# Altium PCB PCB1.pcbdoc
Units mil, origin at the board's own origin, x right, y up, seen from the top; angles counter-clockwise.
Board outline 4730 x 5275 mil, 2 copper layers (Top Layer, Bottom Layer); 23 components, 26 nets, 116 pads, 241 vias.
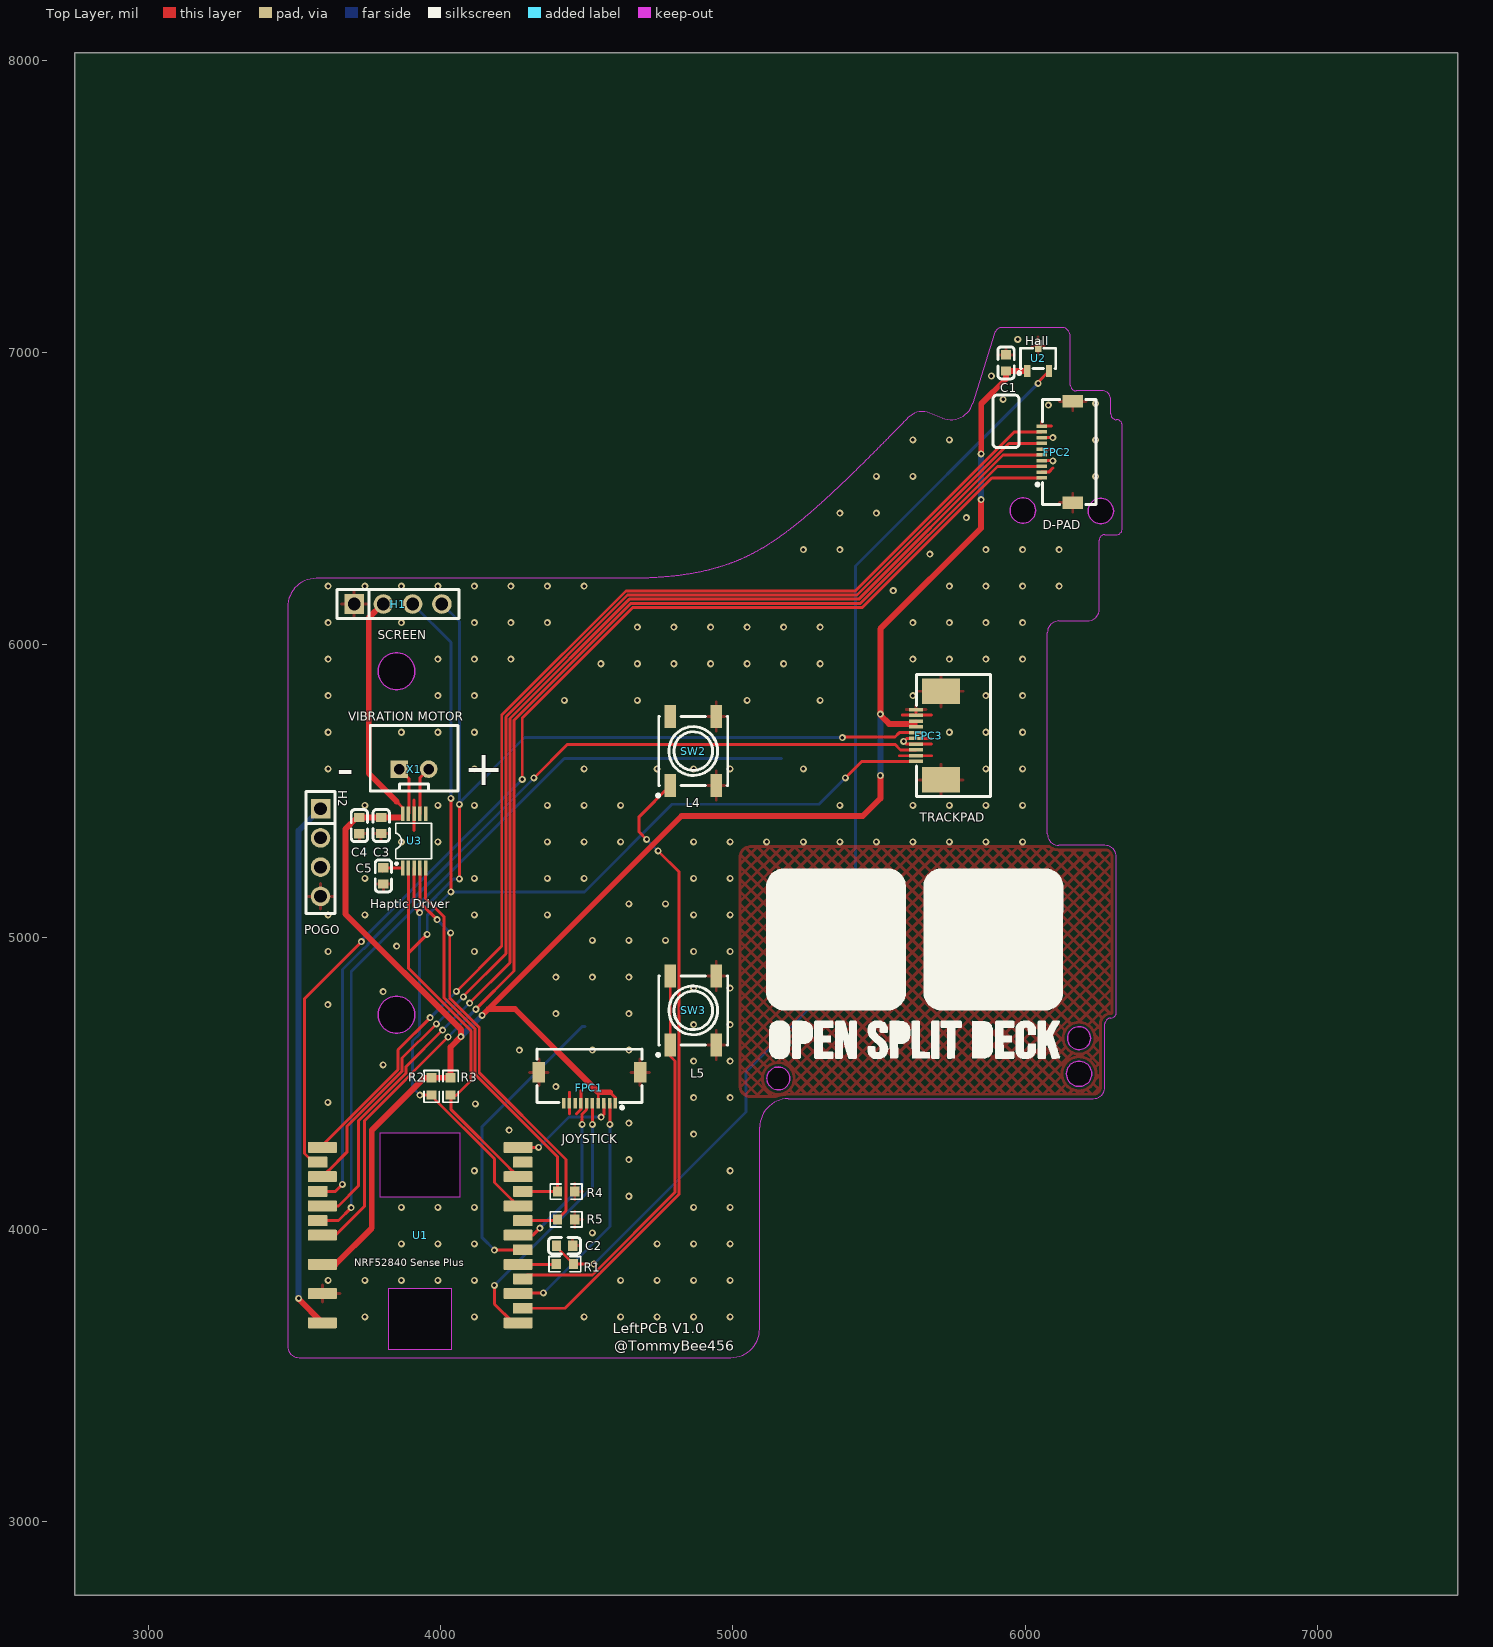
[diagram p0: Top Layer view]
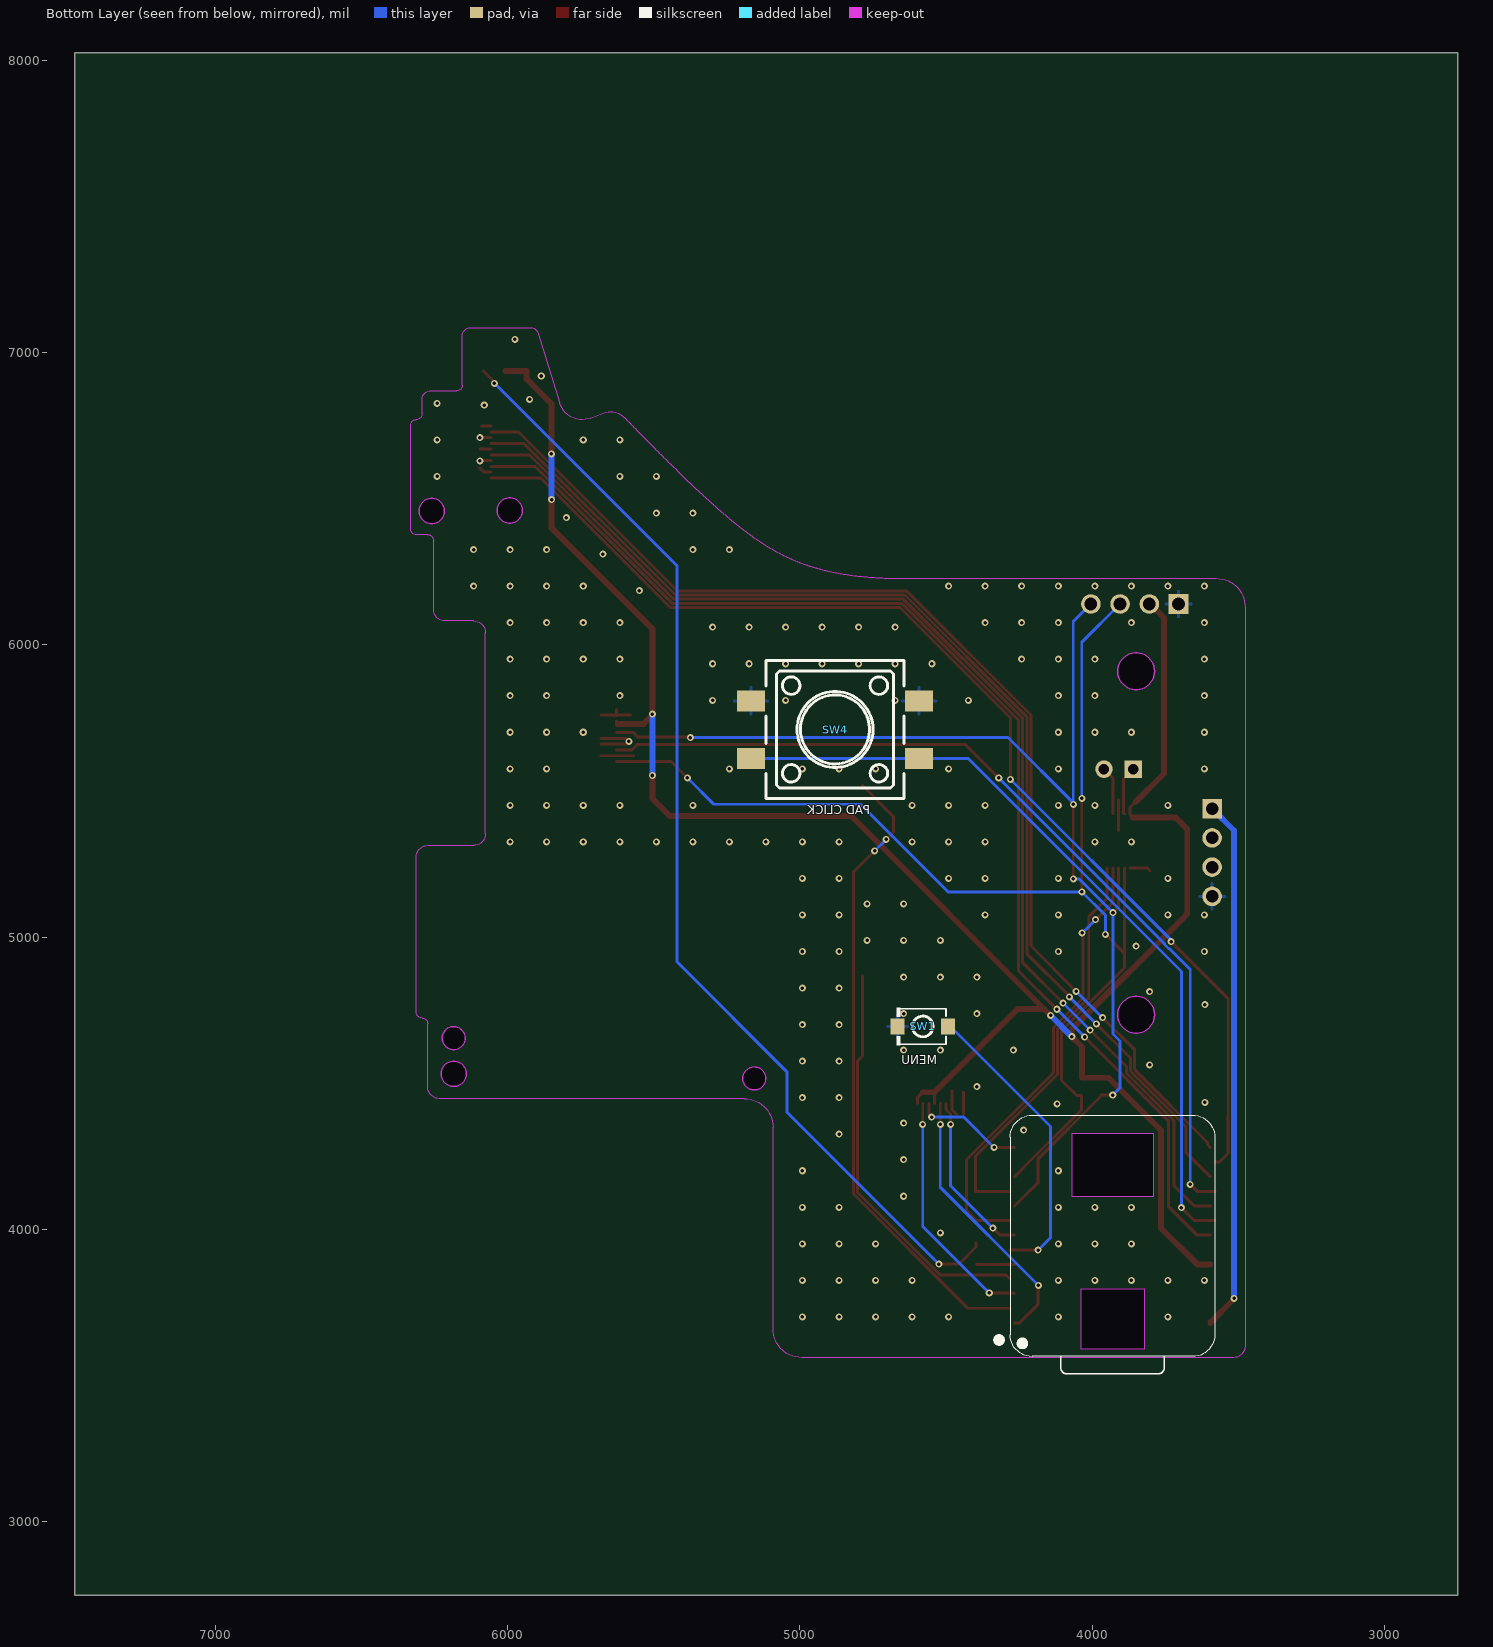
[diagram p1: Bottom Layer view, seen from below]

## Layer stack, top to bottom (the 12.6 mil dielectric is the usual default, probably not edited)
Top Layer: signal copper (thickness not stored)
Dielectric: dielectric 12.6, FR-4, Dk 4.8
Bottom Layer: signal copper (thickness not stored)

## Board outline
7480,2750 2750,2750 2750,8025 7480,8025
cut-out: 5195.47,4517 cw(c5156.1,4517) 5116.73,4517 cw(c5156.1,4517)
cut-out: 6302.57,6458 cw(c6259.26,6458) 6215.95,6458 cw(c6259.26,6458)
cut-out: 6227.91,4533 cw(c6184.61,4533) 6141.3,4533 cw(c6184.61,4533)
cut-out: 6036.03,6460 cw(c5992.72,6460) 5949.41,6460 cw(c5992.72,6460)
cut-out: 6223.98,4655 cw(c6184.61,4655) 6145.24,4655 cw(c6184.61,4655)
cut-out: 3913,5910 cw(c3850,5910) 3787,5910 cw(c3850,5910)
cut-out: 3913,4735 cw(c3850,4735) 3787,4735 cw(c3850,4735)

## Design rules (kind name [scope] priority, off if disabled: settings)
BoardOutlineClearance copperThickness1oz [All] p0: genericclearance=10 ignorepadtopadclearanceinfootprint=FALSE except(0: Arc-SplitContinuation Track-SplitContinuation SMDPad-SplitContinuation THPad-SplitContinuation Via-SplitContinuation Fill-SplitContinuation Poly-SplitContinuation Region-SplitContinuation Text-SplitContinuation; 6: Track-CutoutEdge SMDPad-CutoutEdge THPad-CutoutEdge Via-CutoutEdge Region-CutoutEdge; 11.8: Track-OutlineEdge SMDPad-OutlineEdge THPad-OutlineEdge Via-OutlineEdge Fill-OutlineEdge Region-OutlineEdge Poly-OutlineEdge Text-OutlineEdge Fill-CutoutEdge)
BoardOutlineClearance copperThickness2oz [All] p0: genericclearance=10 ignorepadtopadclearanceinfootprint=FALSE except(0: Arc-SplitContinuation Track-SplitContinuation SMDPad-SplitContinuation THPad-SplitContinuation Via-SplitContinuation Fill-SplitContinuation Poly-SplitContinuation Region-SplitContinuation Text-SplitContinuation; 6: Track-CutoutEdge SMDPad-CutoutEdge THPad-CutoutEdge Via-CutoutEdge Region-CutoutEdge; 11.8: Track-OutlineEdge SMDPad-OutlineEdge THPad-OutlineEdge Via-OutlineEdge Fill-OutlineEdge Region-OutlineEdge Poly-OutlineEdge Text-OutlineEdge Fill-CutoutEdge)
Clearance copperThickness1oz [(InNet('$1N1882') OR InNet('GND') OR InNet('3V3') OR InNet('+5V') OR InNet('STICKCLICK') OR InNet('STICKX') OR InNet('BUMPER') OR InNet('STICKY') OR InNet('START') OR InNet('SCL') OR InNet('SDA') OR InNet('P4') OR InNet('P5') OR InNet('TRIGGER') OR InNet('Y') OR InNet('X') OR InNet('B') OR InNet('A') OR InNet('MODE') OR InNet('HAPTIC_TRIG') OR InNet('DRV_EN') OR InNet('OUT+') OR InNet('OUT-') OR InNet('RDY') OR InNet('PAD_CLICK') OR InNet('$1N6654'))] p1: gap=7 ignorepadtopadclearanceinfootprint=FALSE except(4: Track-Track; 6: Track-SMDPad SMDPad-SMDPad Track-THPad SMDPad-THPad THPad-THPad Track-Via SMDPad-Via THPad-Via Via-Via SMDPad-Fill THPad-Fill Via-Fill Fill-Fill Track-Region SMDPad-Region THPad-Region Via-Region Region-Region Track-Poly SMDPad-Poly THPad-Poly Via-Poly Fill-Poly Region-Poly Poly-Poly Track-Text SMDPad-Text THPad-Text Via-Text Fill-Text Region-Text Poly-Text Text-Text; 6.9: Track-Hole SMDPad-Hole THPad-Hole Via-Hole Fill-Hole Region-Hole Poly-Hole Text-Hole Sheet-Hole; 11.8: Track-Fill Fill-Region Track-Sheet SMDPad-Sheet THPad-Sheet Via-Sheet Fill-Sheet Region-Sheet Poly-Sheet Text-Sheet)
Clearance copperThickness2oz [All] p1: gap=7 ignorepadtopadclearanceinfootprint=FALSE except(6: Track-SMDPad SMDPad-SMDPad Track-THPad SMDPad-THPad THPad-THPad Track-Via SMDPad-Via THPad-Via Via-Via SMDPad-Fill THPad-Fill Via-Fill Fill-Fill Track-Region SMDPad-Region THPad-Region Via-Region Region-Region Track-Poly SMDPad-Poly THPad-Poly Via-Poly Fill-Poly Region-Poly Poly-Poly Track-Text SMDPad-Text THPad-Text Via-Text Fill-Text Region-Text Poly-Text Text-Text; 6.9: Track-Hole SMDPad-Hole THPad-Hole Via-Hole Fill-Hole Region-Hole Poly-Hole Text-Hole Sheet-Hole; 8: Track-Track; 11.8: Track-Fill Fill-Region Track-Sheet SMDPad-Sheet THPad-Sheet Via-Sheet Fill-Sheet Region-Sheet Poly-Sheet Text-Sheet)
DiffPairsRouting differentialPair [All] p1: maxuncoupledlength=10 minlimit=6 maxlimit=6 mostfreqgap=6 toplayer_minwidth=5 toplayer_prefwidth=10 toplayer_maxwidth=100 bottomlayer_minwidth=5 bottomlayer_prefwidth=10 bottomlayer_maxwidth=100
PasteMaskExpansion pasteMaskExpansion [All] p1: expansion=0
PlaneConnect innerPlane [All] p1: planeconnectstyle=Relief reliefexpansion=20 reliefentries=4 reliefconductorwidth=10 reliefairgap=10
PolygonConnect copperRegion [All] p1: connectstyle=Relief reliefentries=4 reliefconductorwidth=10 polygonreliefangle="90 Angle" airgapwidth=10
RoutingVias viaSize [All] p1: viastyle="Through Hole" holewidth=12.0078 minholewidth=11.811 maxholewidth=248.0314 width=24.0158 minwidth=19.685 maxwidth=393.7008
SolderMaskExpansion solderMaskExpansion [All] p1: useseparateexpansions=TRUE expansion=2 expansionbottom=2
Width copperThickness1oz [All] p1: maxlimit=100 minlimit=5 preferedwidth=10
Width copperThickness2oz [All] p1: maxlimit=100 minlimit=8 preferedwidth=10

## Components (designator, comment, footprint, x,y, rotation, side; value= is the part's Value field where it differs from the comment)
C1 "CC0603KRX7R9BB104" C0603 5935,6965 r270 top
C2 "0603B472K500NT" C0603 4425,3945 r180 top
C3 "CC0603KRX7R9BB104" C0603 3797.56,5382.44 r90 top
C4 "CL10A106KP8NNNC" C0603 3723.04,5381.86 r90 top
C5 "CL10A105KB8NNNC" C0603 3805,5210 r90 top
FPC1 "FPC-05F-10PH15" FPC-SMD_10P-P0.50_XUNPU_FPC-05F-10PH15 4510,4485 r180 top
FPC2 "FPC-05F-10PH15" FPC-SMD_10P-P0.50_XUNPU_FPC-05F-10PH15 6110,6660 r90 top
FPC3 "AFC07-S10ECC-00" FPC-SMD_P0.50-10P_LCS-SJ-H2.0 5670,5690 r270 top
H1 "PM254V-11-04-H85" HDR-TH_4P-P2.54-V-F 3855,6140 r0 top
H2 "PM254V-11-04-H85" HDR-TH_4P-P2.54-V-F 3590,5290 r270 top
R1 "0603WAF1000T5E" R0603 4425.66,3882.26 r180 top
R2 "0603WAF2201T5E_C4190" R0603 3970,4490 r90 top
R3 "0603WAF2201T5E_C4190" R0603 4035,4490 r90 top
R4 "0603WAF2003T5E" R0603 4430,4130 r180 top
R5 "0603WAF2003T5E" R0603 4430,4035 r180 top
SW1 "Start" SW-SMD_L3.9-W3.0-P4.45 4580,4695 r0 bottom
SW2 "EVPBFAC1A000" KEY-SMD_4P-L6.0-W6.0-P4.00-LS6.6 4865,5637 r90 top
SW3 "EVPBFAC1A000" KEY-SMD_4P-L6.0-W6.0-P4.00-LS6.6 4865,4750 r90 top
SW4 "TS-1103S-C-I" KEY-SMD_4P-L12.0-W12.0-P5.00-LS15.4 4880,5710 r0 bottom
U1 "XIAO-nRF52840_Plus_SMD" XIAO-nRF52840-Plus-SMD 3930,3955 r180 top
U2 "A1304ELHLX-T" SOT-23-3_L3.0-W1.9-P0.95-LS2.9-BL 6045,6980 r0 top
U3 "DRV2605LDGSR" VSSOP-10_L3.0-W3.0-P0.50-LS4.9-BL 3910,5330 r0 top
X1 "JST" 2JST2.54 3910,5575 r0 top

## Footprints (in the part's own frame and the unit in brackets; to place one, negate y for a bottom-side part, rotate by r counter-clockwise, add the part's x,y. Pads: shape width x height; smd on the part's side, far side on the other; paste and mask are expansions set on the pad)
2JST2.54 [mil]
  rect 60x60 hole 36: 1(-50,0)
  round 60 hole 36: 2(50,0)
  silkscreen extent -150,-75 150,150
C0603 [mm]
  rect 0.8x0.9 smd: 1(-0.7,0) 2(0.7,0)
  silkscreen extent -1.39,-0.71 1.39,0.71
FPC-SMD_10P-P0.50_XUNPU_FPC-05F-10PH15 [mm]
  rect 0.3x0.9 smd: 1(-2.25,1.35) 2(-1.75,1.35) 3(-1.25,1.35) 4(-0.75,1.35) 5(-0.25,1.35) 6(0.25,1.35) 7(0.75,1.35) 8(1.25,1.35) 9(1.75,1.35) 10(2.25,1.35)
  rect 1.1x1.8 smd: 11(4.4,-1.35) 12(-4.4,-1.35)
  silkscreen extent -4.56,-3.36 4.55,1.84
FPC-SMD_P0.50-10P_LCS-SJ-H2.0 [mm]
  rect 0.3x1.2 smd: 1(2.25,-1.085) 2(1.75,-1.085) 3(1.25,-1.085) 4(0.75,-1.085) 5(0.25,-1.085) 6(-0.25,-1.085) 7(-0.75,-1.085) 8(-1.25,-1.085) 9(-1.75,-1.085) 10(-2.25,-1.085)
  rect 2.2x3.3 smd: 11(-3.85,1.085) 12(3.85,1.085)
  silkscreen extent -5.3,-1.04 5.3,5.37
HDR-TH_4P-P2.54-V-F [mm]
  rect 1.7x1.7 hole 1.1: 1(-3.81,0)
  round 1.7 hole 1.1: 2(-1.27,0) 3(1.27,0) 4(3.81,0)
  silkscreen extent -5.29,-1.27 5.29,1.27
KEY-SMD_4P-L6.0-W6.0-P4.00-LS6.6 [mm]
  rect 2x1 smd: 1(-3,2) 2(3,2) 3(-3,-2) 4(3,-2)
  silkscreen extent -3.99,-3 3,3.18
KEY-SMD_4P-L12.0-W12.0-P5.00-LS15.4 [mm]
  rect 2.4x1.8 smd: 1(-7.3,2.5) 2(7.3,2.5) 3(-7.3,-2.5) 4(7.3,-2.5)
  silkscreen extent -6,-6.02 6,5.98
R0603 [mil]
  rect 31.75x34.02 smd: 1(-29.66,0) 2(29.66,0)
  silkscreen extent -55,-26 55,26
SOT-23-3_L3.0-W1.9-P0.95-LS2.9-BL [mil]
  rect 20.95x40.85 smd: 1(-37.4,-43.36) 2(37.4,-43.36) 3(0.01,43.36)
  silkscreen extent -70,-55 60,35
SW-SMD_L3.9-W3.0-P4.45 [mm]
  rect 1.23x1.36 smd: 1(-2.185,0) 2(2.185,0)
  silkscreen extent -2.03,-1.62 2.25,1.62
VSSOP-10_L3.0-W3.0-P0.50-LS4.9-BL [mm]
  rect 0.3x1.3 smd: 1(-1,-2.35) 2(-0.5,-2.35) 3(0,-2.35) 4(0.5,-2.35) 5(1,-2.35) 6(1,2.35) 7(0.5,2.35) 8(0,2.35) 9(-0.5,2.35) 10(-1,2.35)
  silkscreen extent -1.62,-2.08 1.52,1.54
XIAO-nRF52840-Plus-SMD [mm]
  rrect20% 2.532x0.95 smd: 1(-8.533,6.958) 2(-8.533,4.418) 3(-8.533,1.878) 4(-8.533,-0.662) 5(-8.533,-3.202) 6(-8.533,-5.742) 7(-8.533,-8.282) 8(8.477,-8.282) 9(8.477,-5.742) 10(8.477,-3.202) 11(8.477,-0.662) 12(8.477,1.878) 13(8.477,4.418) 14(8.477,6.958)
  rrect20% 1.732x0.95 smd: 15(-8.933,5.688) 16(-8.933,3.148) 17(-8.933,0.608) 18(-8.933,-1.932) 19(-8.933,-4.472) 20(-8.933,-7.012) 21(8.877,-7.012) 22(8.877,-4.472) 23(8.877,-1.932)
  Board Outline Layer lines w0.025: 3.5,-4 3.5,-9.5 -3.5,-9.5 -3.5,-4 3.5,-4 ; 2.75,9.25 2.75,4 -2.75,4 -2.75,9.25 2.75,9.25
  Board Outline Layer region: -3.5,-9.5 3.5,-9.5 3.5,-4 -3.5,-4
  Board Outline Layer region: -2.75,4 2.75,4 2.75,9.25 -2.75,9.25
  Multi-Layer board cut-out: -3.5,-9.5 3.5,-9.5 3.5,-4 -3.5,-4
  Multi-Layer board cut-out: -2.75,4 2.75,4 2.75,9.25 -2.75,9.25

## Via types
v1: diameter 24.02, hole 12.01, Top Layer to Bottom Layer, 241 vias

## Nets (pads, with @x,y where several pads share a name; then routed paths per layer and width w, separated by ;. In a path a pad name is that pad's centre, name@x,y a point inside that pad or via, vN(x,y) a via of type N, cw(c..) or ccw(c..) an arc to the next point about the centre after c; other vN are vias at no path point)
3V3: C1.2 C3.2 C4.2 FPC1.1 FPC1.4 FPC3.7 FPC3.8 H1.2 R2.2 R3.2 U1.12 U2.1 U3.10 | length 7185.1
  Top Layer w10: 3850,5465 3870.62,5444.38 U3.10 3870.62,5420 3860.62,5410 ; FPC1.4 4540,4432.32 4540,4470 ; 4580,4470 4598.58,4451.42 FPC1.1 ; FPC3.7@5627.28,5724.52 FPC3.8
  Top Layer w20: U1.12 3641.07,3881.07 3765,4005 3765,4340 3944.66,4519.66 R2.2 R3.2 4035,4625 v1(4070,4660) 4070,4685 3675,5080 3675,5370 3714.42,5409.42 C4.2 3723.62,5410 C3.2 3860.62,5410 ; H1.2 3801.96,6140 3755,6093.04 3755,5560 3850,5465 ; v1(4142.43,4732.57) 4164.85,4755 ; 4580,4470 4540,4470 4255,4755 4164.85,4755 ; v1(5505,5553.42) 5505,5475 5445,5415 4824.85,5415 4164.85,4755 ; 5621.81,5730 5535.1,5730 5505,5760.1 v1(5505,5762.99) 5505,6055 5849.36,6399.36 v1(5849.36,6497.38) ; v1(5850,6653.4) 5850,6825 5935,6910 C1.2 6006.8,6937.44 U2.1
  Bottom Layer w20: v1(4070,4660) 4070,4660.15 v1(4142.43,4732.57) ; v1(5505,5553.42) v1(5505,5762.99) ; v1(5849.36,6497.38) 5849.36,6652.76 v1(5850,6653.4)
$1N1882: C5.2 U3.1 | length 72.6
  Top Layer w10: C5.2@3802.42,5226.9 3813,5237.48 U3.1
$1N6654: R1.2 U1.3 | length 130.6
  Top Layer w10: U1.3 4394.81,3881.07 R1.2
+5V: H2.1 U1.14 | length 1823.7
  Top Layer w20: v1(3515,3765) 3515,3762.32 U1.14
  Bottom Layer w20: v1(3515,3765) 3515,5365 H2.1
A: FPC2.7 U1.9 | length 4053.5
  Top Layer w10: U1.9 3616.56,4201.38 3616.95,4201.38 3680,4264.43 3680,4352.36 3869.02,4541.38 3869.02,4586.59 v1(3986.21,4703.79) ; v1(4078.71,4796.29) 4078.71,4798.71 4224.02,4944.02 4224.02,5754.02 4640.49,6170.49 5425.49,6170.49 5944.53,6689.53 FPC2.7
  Bottom Layer w10: v1(3986.21,4703.79) v1(4078.71,4796.29)
B: FPC2.3 U1.11 | length 4223.8
  Top Layer w10: U1.11 3641.07,3981.07 3740,4080 3740,4372.72 v1(4026.14,4658.86) ; v1(4121.21,4753.79) 4252.05,4884.62 4252.05,5742.4 4652.1,6142.46 5437.1,6142.46 5905.43,6610.79 FPC2.3
  Bottom Layer w10: v1(4026.14,4658.86) 4121.07,4753.79 v1(4121.21,4753.79)
BUMPER: FPC1.3 U1.7 | length 377.8
  Top Layer w10: U1.7 v1(4336.07,4281.07) ; v1(4550,4385) 4559.21,4394.21 FPC1.3
  Bottom Layer w10: v1(4336.07,4281.07) 4440,4385 v1(4550,4385)
DRV_EN: R4.2 U1.19 U3.5 | length 1412.9
  Top Layer w10: U3.5 3949.38,5133.14 4012.01,5070.51 4012.01,4792.81 4119.02,4685.81 4119.02,4530.98 4400,4250 R4.2@4400,4130.34 ; U1.19 4399.27,4131.07 R4.2@4400,4130.34 ; R4.2 R4.2@4400,4130.34
GND: C1.1 C2.1 C3.1 C4.1 C5.1 FPC1.7 FPC1.9 FPC1.11 FPC1.12 FPC2.2 FPC2.4 FPC2.6 FPC2.8 FPC2.10 FPC2.11 FPC2.12 FPC3.2 FPC3.4 FPC3.5 FPC3.9 FPC3.10 FPC3.11 FPC3.12 H1.1 H2.4 R4.1 R5.1 SW1.2 SW2.3 SW2.4 SW3.3 SW3.4 SW4.3 SW4.4 U1.13 U2.3 U3.8 | length 886.1
  Top Layer w10: 3910.01,5365 U3.8 3910.01,5470 ; 4441.1,4395 FPC1.9 4441.1,4470 ; 4465,4395 4480.47,4410.47 FPC1.7 4480.47,4475 ; 5570,5621.1 FPC3.2 5680,5621.1 ; 5580,5760 FPC3.9@5627.28,5760 ; FPC3.9 FPC3.9@5627.28,5760 ; FPC3.10 FPC3.9@5627.28,5760 ; 5680,5660.47 FPC3.4 5594.53,5660.47 v1(5585,5670) 5595.15,5680.15 FPC3.5 5680,5680.15 ; 5680,5760 FPC3.9@5627.28,5760 ; FPC2.2 6081.1,6591.1 6095,6605 ; FPC2.4 6094.53,6630.47 v1(6095,6630) ; FPC2.6 6095,6669.84 ; FPC2.8 6094.73,6709.21 v1(6095,6708.94) ; FPC2.10 6090,6748.58
  other v1: 3741.34,3701.34 4116.34,3701.34 4491.34,3701.34 4616.34,3701.34 4741.34,3701.34 4866.34,3701.34 4991.34,3701.34 3616.34,3826.34 3741.34,3826.34 3866.34,3826.34 3991.34,3826.34 4116.34,3826.34 4616.34,3826.34 4741.34,3826.34 4866.34,3826.34 4991.34,3826.34 3866.34,3951.34 3991.34,3951.34 4116.34,3951.34 4741.34,3951.34 4866.34,3951.34 4991.34,3951.34 4520.06,3989.1 3866.34,4076.34 3991.34,4076.34 4116.34,4076.34 4866.34,4076.34 4991.34,4076.34 4645.06,4114.1 4116.34,4201.34 4991.34,4201.34 4645.06,4239.1 4866.34,4326.34 4235,4340 4645.06,4364.1 4120,4430 3615,4434.94 4866.34,4451.34 4991.34,4451.34 4395.06,4489.1 3804.1,4563.87 4866.34,4576.34 4991.34,4576.34 4270.06,4614.1 4520.06,4614.1 4645.06,4614.1 4866.34,4701.34 4991.34,4701.34 4395.06,4739.1 4645.06,4739.1 3615,4770 3804.1,4813.87 4866.34,4826.34 4991.34,4826.34 4395.06,4864.1 4520.06,4864.1 4645.06,4864.1 3616.34,4951.34 4116.34,4951.34 4866.34,4951.34 4991.34,4951.34 3850,4970 4520.06,4989.1 4645.06,4989.1 4770.06,4989.1 3616.34,5076.34 3741.34,5076.34 4116.34,5076.34 4366.34,5076.34 4866.34,5076.34 4991.34,5076.34 4645.06,5114.1 4770.06,5114.1 3741.34,5201.34 4116.34,5201.34 4366.34,5201.34 4491.34,5201.34 4866.34,5201.34 4991.34,5201.34 3866.34,5326.34 3991.34,5326.34 4366.34,5326.34 4491.34,5326.34 4616.34,5326.34 4866.34,5326.34 4991.34,5326.34 5116.34,5326.34 5241.34,5326.34 5366.34,5326.34 5491.34,5326.34 5616.34,5326.34 5741.34,5326.34 5866.34,5326.34 5991.34,5326.34 3741.34,5451.34 3991.34,5451.34 4116.34,5451.34 4366.34,5451.34 4491.34,5451.34 4616.34,5451.34 5366.34,5451.34 5616.34,5451.34 5741.34,5451.34 5866.34,5451.34 5991.34,5451.34 3616.34,5576.34 4116.34,5576.34 4491.34,5576.34 4741.34,5576.34 4866.34,5576.34 4991.34,5576.34 5241.34,5576.34 5866.34,5576.34 5991.34,5576.34 3616.34,5701.34 3866.34,5701.34 3991.34,5701.34 4116.34,5701.34 5741.34,5701.34 5866.34,5701.34 5991.34,5701.34 4424.1,5810.65 4674.1,5810.65 5049.1,5810.65 5299.1,5810.65 3616.34,5826.34 3991.34,5826.34 4116.34,5826.34 5616.34,5826.34 5866.34,5826.34 5991.34,5826.34 4549.1,5935.65 4674.1,5935.65 4799.1,5935.65 4924.1,5935.65 5049.1,5935.65 5174.1,5935.65 5299.1,5935.65 3616.34,5951.34 3991.34,5951.34 4116.34,5951.34 4241.34,5951.34 5616.34,5951.34 5741.34,5951.34 5866.34,5951.34 5991.34,5951.34 4674.1,6060.65 4799.1,6060.65 4924.1,6060.65 5049.1,6060.65 5174.1,6060.65 5299.1,6060.65 3616.34,6076.34 3866.34,6076.34 4116.34,6076.34 4241.34,6076.34 4366.34,6076.34 5616.34,6076.34 5741.34,6076.34 5866.34,6076.34 5991.34,6076.34 5549.1,6185.65 3616.34,6201.34 3741.34,6201.34 3866.34,6201.34 3991.34,6201.34 4116.34,6201.34 4241.34,6201.34 4366.34,6201.34 4491.34,6201.34 5741.34,6201.34 5866.34,6201.34 5991.34,6201.34 6116.34,6201.34 5674.1,6310.65 5241.34,6326.34 5366.34,6326.34 5866.34,6326.34 5991.34,6326.34 6116.34,6326.34 5799.1,6435.65 5366.34,6451.34 5491.34,6451.34 5491.34,6576.34 5616.34,6576.34 6241.34,6576.34 5616.34,6701.34 5741.34,6701.34 6241.34,6701.34 6080,6820 6241.34,6826.34 5925,6840 5885,6920 5975,7045
HAPTIC_TRIG: R5.2 U1.18 U3.4 | length 1545.3
  Top Layer w10: U3.4 3929.68,5119.33 v1(3989.02,5060) ; v1(4035,5015) 4032.01,5012.01 4032.01,4792.63 4133.03,4691.61 4133.03,4536.79 4430,4239.82 4430,4064.66 R5.2 4396.41,4031.07 U1.18
  Bottom Layer w10: v1(3989.02,5060) 4034.02,5015 v1(4035,5015)
MODE: SW1.1 U1.17 | length 1030.1
  Top Layer w10: v1(4185,3930) 4280.61,3930 U1.17
  Bottom Layer w10: v1(4185,3930) 4143.03,3971.97 4143.03,4353.03 4485,4695 SW1.1
OUT+: U3.7 X1.2 | length 165
  Top Layer w10: U3.7 3929.68,5544.69 X1.2
OUT-: U3.9 X1.1 | length 167.4
  Top Layer w10: X1.1 3893.12,5541.88 3893.12,5425.32 U3.9
P4: SW2.1 U1.15 | length 2194.9
  Top Layer w10: U1.15 4426.14,3731.07 4816.93,4121.85 4816.93,5223.07 v1(4744.72,5295.28) ; v1(4705.13,5334.87) 4680,5360 4680,5412.63 SW2.1
  Bottom Layer w10: v1(4705.13,5334.87) v1(4744.72,5295.28)
P5: SW3.1 SW3.2 U1.16 | length 1391.4
  Top Layer w10: U1.16 4295.61,3845 4520.25,3845 4802.91,4127.66 4802.91,4577.09 4786.26,4593.74 SW3.2
PAD_CLICK: SW4.1 SW4.2 U1.23 | length 2714.6
  Top Layer w10: U1.23 3651.07,4031.07 v1(3695,4075)
  Bottom Layer w10: v1(3695,4075) 3695,4882.52 4424.06,5611.57 SW4.1 SW4.2
RDY: FPC3.3 U1.22 | length 3120.1
  Top Layer w10: U1.22 3641.07,4131.07 v1(3665,4155) ; v1(4320,5545) 4435,5660 5555,5660 5574.22,5640.78 FPC3.3
  Bottom Layer w10: v1(3665,4155) 3665,4890 3737.01,4962.01 3739.52,4962.01 3752.99,4975.48 3752.99,4977.99 v1(4320,5545)
SCL: FPC3.1 H1.3 R3.1 U1.6 U3.2 | length 4364.5
  Top Layer w10: U3.2 3890.32,4945.31 ; v1(3955,5010) 3890.32,4945.31 ; v1(4035.98,5155) v1(4035.98,5475) ; U1.6 4245.62,4201.38 4245.23,4201.38 4236.6,4210.01 4236.6,4210.4 4036.82,4410.18 4036.82,4458.45 4053.45,4458.45 4105,4510 4105,4680 3890.32,4894.69 3890.32,4945.31 ; v1(5385,5545) 5441.41,5601.41 FPC3.1
  Bottom Layer w10: H1.3 4035.98,6009.02 v1(4035.98,5475) ; v1(3955,5010) 3955,5075 4035,5155 v1(4035.98,5155) 4492.75,5155 4792.75,5455 5295,5455 v1(5385,5545)
SDA: FPC3.6 H1.4 R2.1 U1.5 U3.3 | length 4157.8
  Top Layer w10: U3.3 3910,5103.31 v1(3929.15,5084.15) ; v1(3930,4460.34) R2.1 3970,4457.18 4185,4242.18 4185,4161.61 4245.23,4101.38 4245.62,4101.38 U1.5 ; v1(4065,5200) v1(4065,5455) ; v1(5375,5682.99) 5377.01,5685 5555,5685 5569.84,5699.84 FPC3.6
  Bottom Layer w10: v1(3930,4460.34) 3905,4485.34 3905,4645 3929.15,4669.15 v1(3929.15,5084.15) 4045,5200 v1(4065,5200) ; H1.4 4065,6080 v1@4065,5460 ; v1(4065,5455) v1@4065,5460 ; v1(5375,5682.99) 4287.99,5682.99 v1@4065,5460
START: FPC2.9 U1.8 | length 3981.3
  Top Layer w10: U1.8 3606.25,4291.07 3606.25,4298.43 3855,4547.18 3855,4615 v1(3965,4725) ; v1(4055,4815) 4210,4970 4210,5760 4635,6185 5419.12,6185 5963.02,6728.9 FPC2.9
  Bottom Layer w10: v1(3965,4725) v1(4055,4815)
STICKCLICK: FPC1.6 U1.4 | length 577.2
  Top Layer w10: U1.4 4316.07,3981.07 v1(4340,4005) ; v1(4485,4360) 4485,4395 4500.16,4410.16 FPC1.6
  Bottom Layer w10: v1(4340,4005) 4485,4150 v1(4485,4360)
STICKX: FPC1.5 U1.1 | length 933.7
  Top Layer w10: v1(4184.29,3809.29) 4185,3808.58 4185,3745 4248.93,3681.07 U1.1 ; FPC1.5 4520,4431.69 v1(4520,4360)
  Bottom Layer w10: v1(4184.29,3809.29) 4520,4145 v1(4520,4360)
STICKY: FPC1.2 U1.2 | length 830.6
  Top Layer w10: U1.2 4268.43,3783.57 v1(4352.5,3783.57) ; FPC1.2 4580,4430.75 v1(4580,4360)
  Bottom Layer w10: v1(4352.5,3783.57) 4580,4011.07 v1(4580,4360)
TRIGGER: C2.2 R1.1 U2.2 | length 3865.9
  Top Layer w10: C2.2@4397.44,3955 4397.44,3940.15 R1.1 v1(4525,3882.26) ; v1(6045,6895) 6045,6899.24 U2.2
  Bottom Layer w10: v1(4525,3882.26) 5045,4402.26 5045,4540 5420,4915 5420,6270 v1(6045,6895)
X: FPC2.5 U1.10 | length 4157.6
  Top Layer w10: U1.10 3651.07,4081.07 3720,4150 3720,4372.54 3883.03,4535.57 3883.03,4558.18 v1(4007.43,4682.57) ; v1(4100,4775) 4238.03,4913.03 4238.03,5748.21 4646.3,6156.48 5431.3,6156.48 5924.98,6650.16 FPC2.5
  Bottom Layer w10: v1(4007.43,4682.57) 4007.57,4682.57 v1(4100,4775)
Y: FPC2.1 U1.21 | length 3973.2
  Top Layer w10: U1.21 3564.36,4231.07 3535.42,4260.01 3535.42,4389.58 3535,4390 3535,4790 v1(3730,4985) ; v1(4280,5540) 4280,5750.54 4657.91,6128.45 5443.45,6128.45 5886.42,6571.42 FPC2.1
  Bottom Layer w10: v1(3730,4985) 3730,4990 v1(4280,5540)
pads on no net: FPC1.8 FPC1.10 H2.2 H2.3 SW2.2 U1.20 U3.6

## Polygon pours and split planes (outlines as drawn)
GND on Top Layer (hatched 45Degree grid 30 track 10, pour order 0): 5060,5315 6275,5315 cw(c6275,5275) 6315,5275 6315,4490 cw(c6275,4490) 6275,4450 5060,4450 cw(c5060,4490) 5020,4490 5020,5275 cw(c5060,5275)
GND on Bottom Layer (solid, remove dead copper, pour order 4): 3000,7470 3000,3340 3340,3000 6975,3000 7230,3255 7230,7495 6955,7770 3300,7770
GND on Top Layer (solid, remove dead copper, pour order 2): 3345,6370 3345,3470 3420,3395 5285,3395 5275.58,4455 5051.78,4455 5026.72,4468.8 5025,4480.48 5025,5280 5036.44,5303.28 5055.67,5310.21 6205.29,5310.21 6555,5666.23 6555,7775 4750,7775

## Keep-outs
Board Outline Layer:
  circle w1: c5156.1,4517 r39.37
  region: 5195.47,4517 cw(c5156.1,4517) 5116.73,4517 cw(c5156.1,4517)
  circle w1: c6259.26,6458 r43.31
  region: 6302.57,6458 cw(c6259.26,6458) 6215.95,6458 cw(c6259.26,6458)
  circle w1: c6184.61,4533 r43.31
  region: 6227.91,4533 cw(c6184.61,4533) 6141.3,4533 cw(c6184.61,4533)
  circle w1: c5992.72,6460 r43.31
  region: 6036.03,6460 cw(c5992.72,6460) 5949.41,6460 cw(c5992.72,6460)
  circle w1: c6184.61,4655 r39.37
  region: 6223.98,4655 cw(c6184.61,4655) 6145.24,4655 cw(c6184.61,4655)
  circle w1: c3850,5910 r63
  region: 3913,5910 cw(c3850,5910) 3787,5910 cw(c3850,5910)
  circle w1: c3850,4735 r63
  region: 3913,4735 cw(c3850,4735) 3787,4735 cw(c3850,4735)
  lines w3.9: 3752.84,3562.24 4107.17,3562.24
  lines w3.94: 3752.84,3562.24 3516.61,3562.24 cw(c3516.61,3601.61) 3477.24,3601.61 3477.24,6129.05 cw(c3575.67,6129.05) 3575.67,6227.48 4638.66,6227.48 4643.16,6227.48 4647.63,6227.5 4652.08,6227.52 4656.51,6227.56 4660.92,6227.61 4665.3,6227.66 4669.67,6227.73 4674.01,6227.81 4678.34,6227.9 4682.64,6228 4686.92,6228.11 4691.18,6228.23 4695.41,6228.36 4699.63,6228.5 4703.83,6228.65 4708,6228.81 4712.16,6228.98 4716.29,6229.17 4720.4,6229.36 4724.49,6229.56 4728.57,6229.78 4732.62,6230 4736.65,6230.23 4740.66,6230.48 4744.64,6230.73 4748.61,6231 4752.56,6231.28 4756.49,6231.56 4760.4,6231.86 4764.29,6232.17 4768.16,6232.48 4772,6232.81 4775.83,6233.15 4779.64,6233.5 4783.43,6233.86 4787.2,6234.23 4790.95,6234.6 4794.69,6234.99 4798.4,6235.4 4802.09,6235.81 4805.77,6236.23 4809.43,6236.66 4813.06,6237.1 4816.68,6237.55 4820.28,6238.02 4823.87,6238.49 4827.43,6238.97 4830.98,6239.47 4834.51,6239.97 4838.02,6240.48 4841.51,6241.01 4844.99,6241.54 4848.45,6242.09 4851.89,6242.65 4855.32,6243.21 4858.73,6243.79 4862.12,6244.38 4865.49,6244.98 4868.85,6245.58 4872.19,6246.2 4875.52,6246.83 4878.83,6247.47 4882.13,6248.12 4885.4,6248.78 4888.67,6249.46 4891.92,6250.14 4895.15,6250.83 4898.37,6251.53 4901.57,6252.25 4904.76,6252.97 4907.93,6253.7 4911.09,6254.45 4914.24,6255.21 4917.37,6255.97 4920.49,6256.75 4923.59,6257.54 4926.68,6258.34 4929.76,6259.15 4932.82,6259.97 4935.87,6260.8 4938.91,6261.64 4941.94,6262.49 4944.95,6263.36 4947.95,6264.23 4950.94,6265.12 4953.91,6266.01 4956.88,6266.92 4959.83,6267.84 4962.77,6268.77 4965.7,6269.71 4968.62,6270.66 4971.53,6271.62 4974.43,6272.59 4977.32,6273.58 4980.2,6274.57 4983.06,6275.58 4985.92,6276.6 4988.77,6277.63 4991.61,6278.67 4994.43,6279.72 4997.25,6280.78 5000.06,6281.86 5002.87,6282.94 5005.66,6284.04 5008.44,6285.15 5011.22,6286.27 5013.99,6287.41 5016.75,6288.55 5019.51,6289.71 5022.25,6290.87 5024.99,6292.05 5027.72,6293.24 5030.45,6294.45 5033.17,6295.66 5035.88,6296.89 5038.58,6298.13 5041.28,6299.38 5043.98,6300.64 5046.67,6301.92 5049.35,6303.21 5052.03,6304.51 5054.7,6305.82 5057.37,6307.15 5060.03,6308.48 5062.69,6309.83 5065.35,6311.19 5068,6312.57 5070.65,6313.96 5073.29,6315.36 5075.93,6316.77 5078.57,6318.2 5081.2,6319.64 5083.83,6321.09 5086.46,6322.56 5089.09,6324.03 5091.71,6325.53 5094.34,6327.03 5096.96,6328.55 5099.57,6330.08 5102.19,6331.62 5104.81,6333.18 5107.43,6334.76 5110.04,6336.34 5112.65,6337.94 5115.27,6339.56 5117.88,6341.18 5120.5,6342.82 5123.11,6344.48 5125.73,6346.15 5128.34,6347.83 5130.96,6349.53 5133.58,6351.24 5136.2,6352.97 5138.82,6354.71 5141.44,6356.47 5144.06,6358.24 5146.69,6360.02 5149.32,6361.82 5151.95,6363.64 5154.58,6365.47 5157.22,6367.31 5159.86,6369.18 5162.5,6371.05 5165.15,6372.94 5167.8,6374.85 5170.46,6376.77 5173.12,6378.71 5175.78,6380.66 5178.45,6382.63 5181.12,6384.62 5183.8,6386.62 5186.48,6388.64 5189.17,6390.67 5191.86,6392.72 5194.56,6394.78 5197.27,6396.87 5199.98,6398.97 5202.7,6401.08 5205.42,6403.21 5208.16,6405.36 5210.9,6407.53 5213.64,6409.71 5216.39,6411.91 5219.16,6414.13 5221.92,6416.37 5224.7,6418.62 5227.49,6420.89 5230.28,6423.18 5233.08,6425.48 5235.89,6427.8 5238.71,6430.15 5241.54,6432.5 5244.38,6434.88 5247.23,6437.28 5250.08,6439.69 5252.95,6442.12 5255.83,6444.57 5258.71,6447.04 5261.61,6449.53 5264.52,6452.04 5267.44,6454.57 5270.37,6457.11 5273.31,6459.68 5276.27,6462.26 5279.23,6464.86 5282.21,6467.49 5285.2,6470.13 5288.2,6472.79 5291.21,6475.47 5294.24,6478.18 5297.28,6480.9 5300.33,6483.64 5303.39,6486.4 5306.47,6489.18 5309.56,6491.99 5312.66,6494.81 5315.78,6497.66 5318.91,6500.52 5322.06,6503.41 5325.22,6506.31 5328.39,6509.24 5331.58,6512.19 5334.79,6515.16 5338.01,6518.16 5341.24,6521.17 5344.49,6524.2 5347.76,6527.26 5351.04,6530.34 5354.33,6533.44 5357.64,6536.56 5360.97,6539.71 5364.32,6542.88 5367.68,6546.07 5371.05,6549.28 5374.45,6552.51 5377.86,6555.77 5381.28,6559.05 5384.73,6562.35 5388.19,6565.68 5391.67,6569.03 5395.16,6572.4 5398.68,6575.8 5402.21,6579.21 5405.76,6582.66 5409.33,6586.12 5412.91,6589.61 5416.52,6593.12 5420.14,6596.66 5423.78,6600.22 5427.44,6603.81 5431.12,6607.41 5434.82,6611.05 5438.54,6614.7 5442.27,6618.39 5446.03,6622.09 5449.8,6625.82 5453.6,6629.58 5457.41,6633.36 5461.24,6637.16 5465.1,6640.99 5468.97,6644.84 5472.86,6648.72 5476.78,6652.63 5480.71,6656.55 5484.66,6660.51 5488.64,6664.49 5492.63,6668.49 5496.65,6672.52 5500.69,6676.58 5504.74,6680.66 5508.82,6684.76 5512.92,6688.9 5517.04,6693.05 5521.18,6697.24 5525.34,6701.45 5529.52,6705.68 5533.73,6709.94 5537.95,6714.23 5542.2,6718.54 5546.46,6722.88 5550.75,6727.24 5555.06,6731.63 5559.39,6736.05 5563.75,6740.49 5568.12,6744.96 5572.52,6749.45 5576.94,6753.97 5581.38,6758.52 5585.84,6763.09 5590.32,6767.69 5594.82,6772.32 5599.35,6776.97 cw(c5648.74,6728.93) 5673.87,6793.08 5717.07,6776.16 ccw(c5745.79,6849.47) 5821.02,6826.22 5894.84,7065.05 cw(c5923.05,7056.33) 5923.05,7085.86 6125.55,7085.86 cw(c6125.55,7056.33) 6155.08,7056.33 6155.08,6889.01 ccw(c6174.76,6889.01) 6174.76,6869.32 6263.35,6869.32 cw(c6263.35,6839.8) 6292.87,6839.8 6292.87,6790.58 ccw(c6312.56,6790.58) 6312.56,6770.9 cw(c6312.56,6751.21) 6332.24,6751.21 6332.24,6396.88 cw(c6312.56,6396.88) 6312.56,6377.2 6273.19,6377.2 ccw(c6273.19,6357.51) 6253.5,6357.51 6253.5,6121.29 cw(c6214.13,6121.29) 6214.13,6081.92 6115.71,6081.92 ccw(c6115.71,6042.55) 6076.34,6042.55 6076.34,5353.58 ccw(c6115.71,5353.58) 6115.71,5314.21 6273.19,5314.21 cw(c6273.19,5274.84) 6312.56,5274.84 6312.56,4743.34 cw(c6292.87,4743.34) 6292.87,4723.65 ccw(c6292.87,4703.97) 6273.19,4703.97 6273.19,4487.43 cw(c6233.82,4487.43) 6233.82,4448.06 5190.51,4448.06 ccw(c5190.51,4349.64) 5092.09,4349.64 5092.09,3660.66 cw(c4993.66,3660.66) 4993.66,3562.24 4107.17,3562.24

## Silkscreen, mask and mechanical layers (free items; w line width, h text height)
Top Silkscreen Layer:
  drawing of 32 lines, arcs and shapes, not listed
  text "Hall" at 6000,7025 h30
  text "D-PAD" at 6060,6395 h30
  text "SCREEN" at 3785,6020 h30
  text "VIBRATION MOTOR" at 3685,5740 h30
  text "-" at 3644.92,5520 h120
  text "+" at 4080,5520 h120
  text "L4" at 4840,5445 h30
  text "TRACKPAD" at 5640,5395 h30
  text "Haptic Driver" at 3760,5100 h30
  text "POGO" at 3535,5010 h30
  text "L5" at 4855,4520 h30
  text "JOYSTICK" at 4415,4295 h30
  text "NRF52840 Sense Plus" at 3705,3875 h25
  text "LeftPCB V1.0" at 4590,3645 h35
  text "@TommyBee456" at 4595,3585 h35
Bottom Silkscreen Layer:
  text "PAD CLICK" at 4760,5420 h30
  text "MENU" at 4530,4565 h30
Mechanical Layer:
  circle w1: c5156.1,4517 r39.37
  circle w1: c6259.26,6458 r43.31
  circle w1: c6184.61,4533 r43.31
  circle w1: c5992.72,6460 r43.31
  circle w1: c6184.61,4655 r39.37
  circle w1: c3850,5910 r63
  circle w1: c3850,4735 r63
